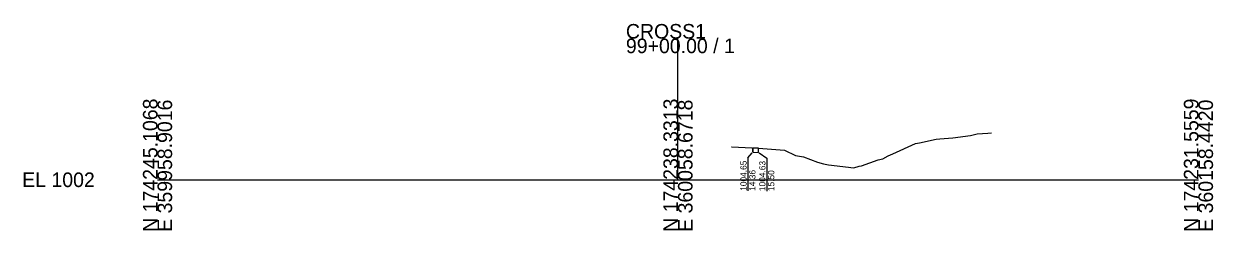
# Model space of a CAD drawing. Extents: x -26 to 1403, y -10 to 11027.
# Drawn here: x 1174.3 to 1402.8, y 2490.3 to 2530 of the extents above; entities that cross this region are included whole.
import ezdxf

# ---------------------------------------------------------------- set-up
doc = ezdxf.new("R2010")
doc.units = 0
for name, color, linetype in [('Default', 7, 'Continuous'), ('P_E_XS_Ground', 7, 'Continuous'), ('P_XS_EAR_CommonGrnd', 7, 'Continuous'), ('P_XS_Lane', 7, 'Continuous'), ('P_XS_Rock', 7, 'Continuous')]:
    doc.layers.add(name, color=color, linetype=linetype)

msp = doc.modelspace()

# ---------------------------------------------------------------- linework, layer by layer
at = {"layer": 'Default'}
for p, q in [((1300, 2500), (1300, 2527.13)), ((1200, 2500), (1300, 2500)), ((1300, 2500), (1400, 2500))]:
    msp.add_line(p, q, dxfattribs=at)
at = {"layer": 'P_E_XS_Ground'}
for p, q in [((1345.67, 2506.96), (1346.4, 2507.11)), ((1346.4, 2507.11), (1349.58, 2507.8)), ((1349.58, 2507.8), (1350.29, 2507.87)), ((1350.29, 2507.87), (1352.83, 2508.05)), ((1352.83, 2508.05), (1356.19, 2508.49)), ((1356.19, 2508.49), (1357.48, 2508.82)), ((1357.48, 2508.82), (1359.51, 2508.98)), ((1359.51, 2508.98), (1360.22, 2509.04)), ((1310.26, 2506.31), (1310.36, 2506.3)), ((1310.36, 2506.3), (1315.5, 2506.1)), ((1315.5, 2506.1), (1320.5, 2505.7)), ((1320.5, 2505.7), (1322.61, 2504.64)), ((1340.39, 2504.62), (1341.28, 2504.97)), ((1341.28, 2504.97), (1345.67, 2506.96)), ((1322.61, 2504.64), (1324.11, 2504.41)), ((1324.11, 2504.41), (1326.78, 2503.38)), ((1326.78, 2503.38), (1327.96, 2503.04)), ((1327.96, 2503.04), (1328.9, 2502.88)), ((1328.9, 2502.88), (1332.75, 2502.44)), ((1332.75, 2502.44), (1333.22, 2502.35)), ((1333.81, 2502.27), (1334.8, 2502.61)), ((1334.8, 2502.61), (1335.26, 2502.7)), ((1335.26, 2502.7), (1338.46, 2503.83)), ((1338.46, 2503.83), (1339.33, 2504.05)), ((1339.33, 2504.05), (1340.39, 2504.62)), ((1333.22, 2502.35), (1333.81, 2502.27))]:
    msp.add_line(p, q, dxfattribs=at)
at = {"layer": 'P_XS_EAR_CommonGrnd'}
msp.add_lwpolyline([(1314.36, 2505.31), (1315.5, 2505.26), (1315.5, 2506.1), (1314.36, 2506.14)], close=True, dxfattribs=at)
at = {"layer": 'P_XS_Lane'}
for p, q in [((1314.36, 2505.31), (1314.36, 2506.14)), ((1314.36, 2505.31), (1315.5, 2505.26)), ((1315.5, 2505.26), (1315.5, 2506.1))]:
    msp.add_line(p, q, dxfattribs=at)
at = {"layer": 'P_XS_Rock'}
for p, q in [((1313.44, 2504.22), (1314.26, 2505.19)), ((1315.6, 2505.2), (1317.06, 2504.17)), ((1313.44, 2504.22), (1313.44, 2497.87)), ((1317.06, 2504.17), (1317.06, 2497.82))]:
    msp.add_line(p, q, dxfattribs=at)

# ---------------------------------------------------------------- texts
at = {"layer": 'Default'}
for s, p in [('CROSS1', (1290, 2527.13)), ('99+00.00 / 1', (1290, 2524.33)), ('EL 1002', (1174, 2498.6))]:
    msp.add_text(s, height=2.8, dxfattribs=at).set_placement(p)
for s, p in [('N 174245.1068', (1200, 2490)), ('E 359958.9016', (1202.8, 2490)), ('N 174238.3313', (1300, 2490)), ('E 360058.6718', (1302.8, 2490)), ('N 174231.5559', (1400, 2490)), ('E 360158.4420', (1402.8, 2490))]:
    msp.add_text(s, height=2.8, rotation=90, dxfattribs=at).set_placement(p)
at = {"layer": 'P_XS_Rock'}
for s, p in [('1004.65', (1313.19, 2497.87)), ('1004.63', (1316.81, 2497.82)), ('14.36', (1314.89, 2497.87)), ('15.50', (1318.51, 2497.82))]:
    msp.add_text(s, height=1.2, rotation=90, dxfattribs=at).set_placement(p)

doc.saveas('drawing.dxf')
